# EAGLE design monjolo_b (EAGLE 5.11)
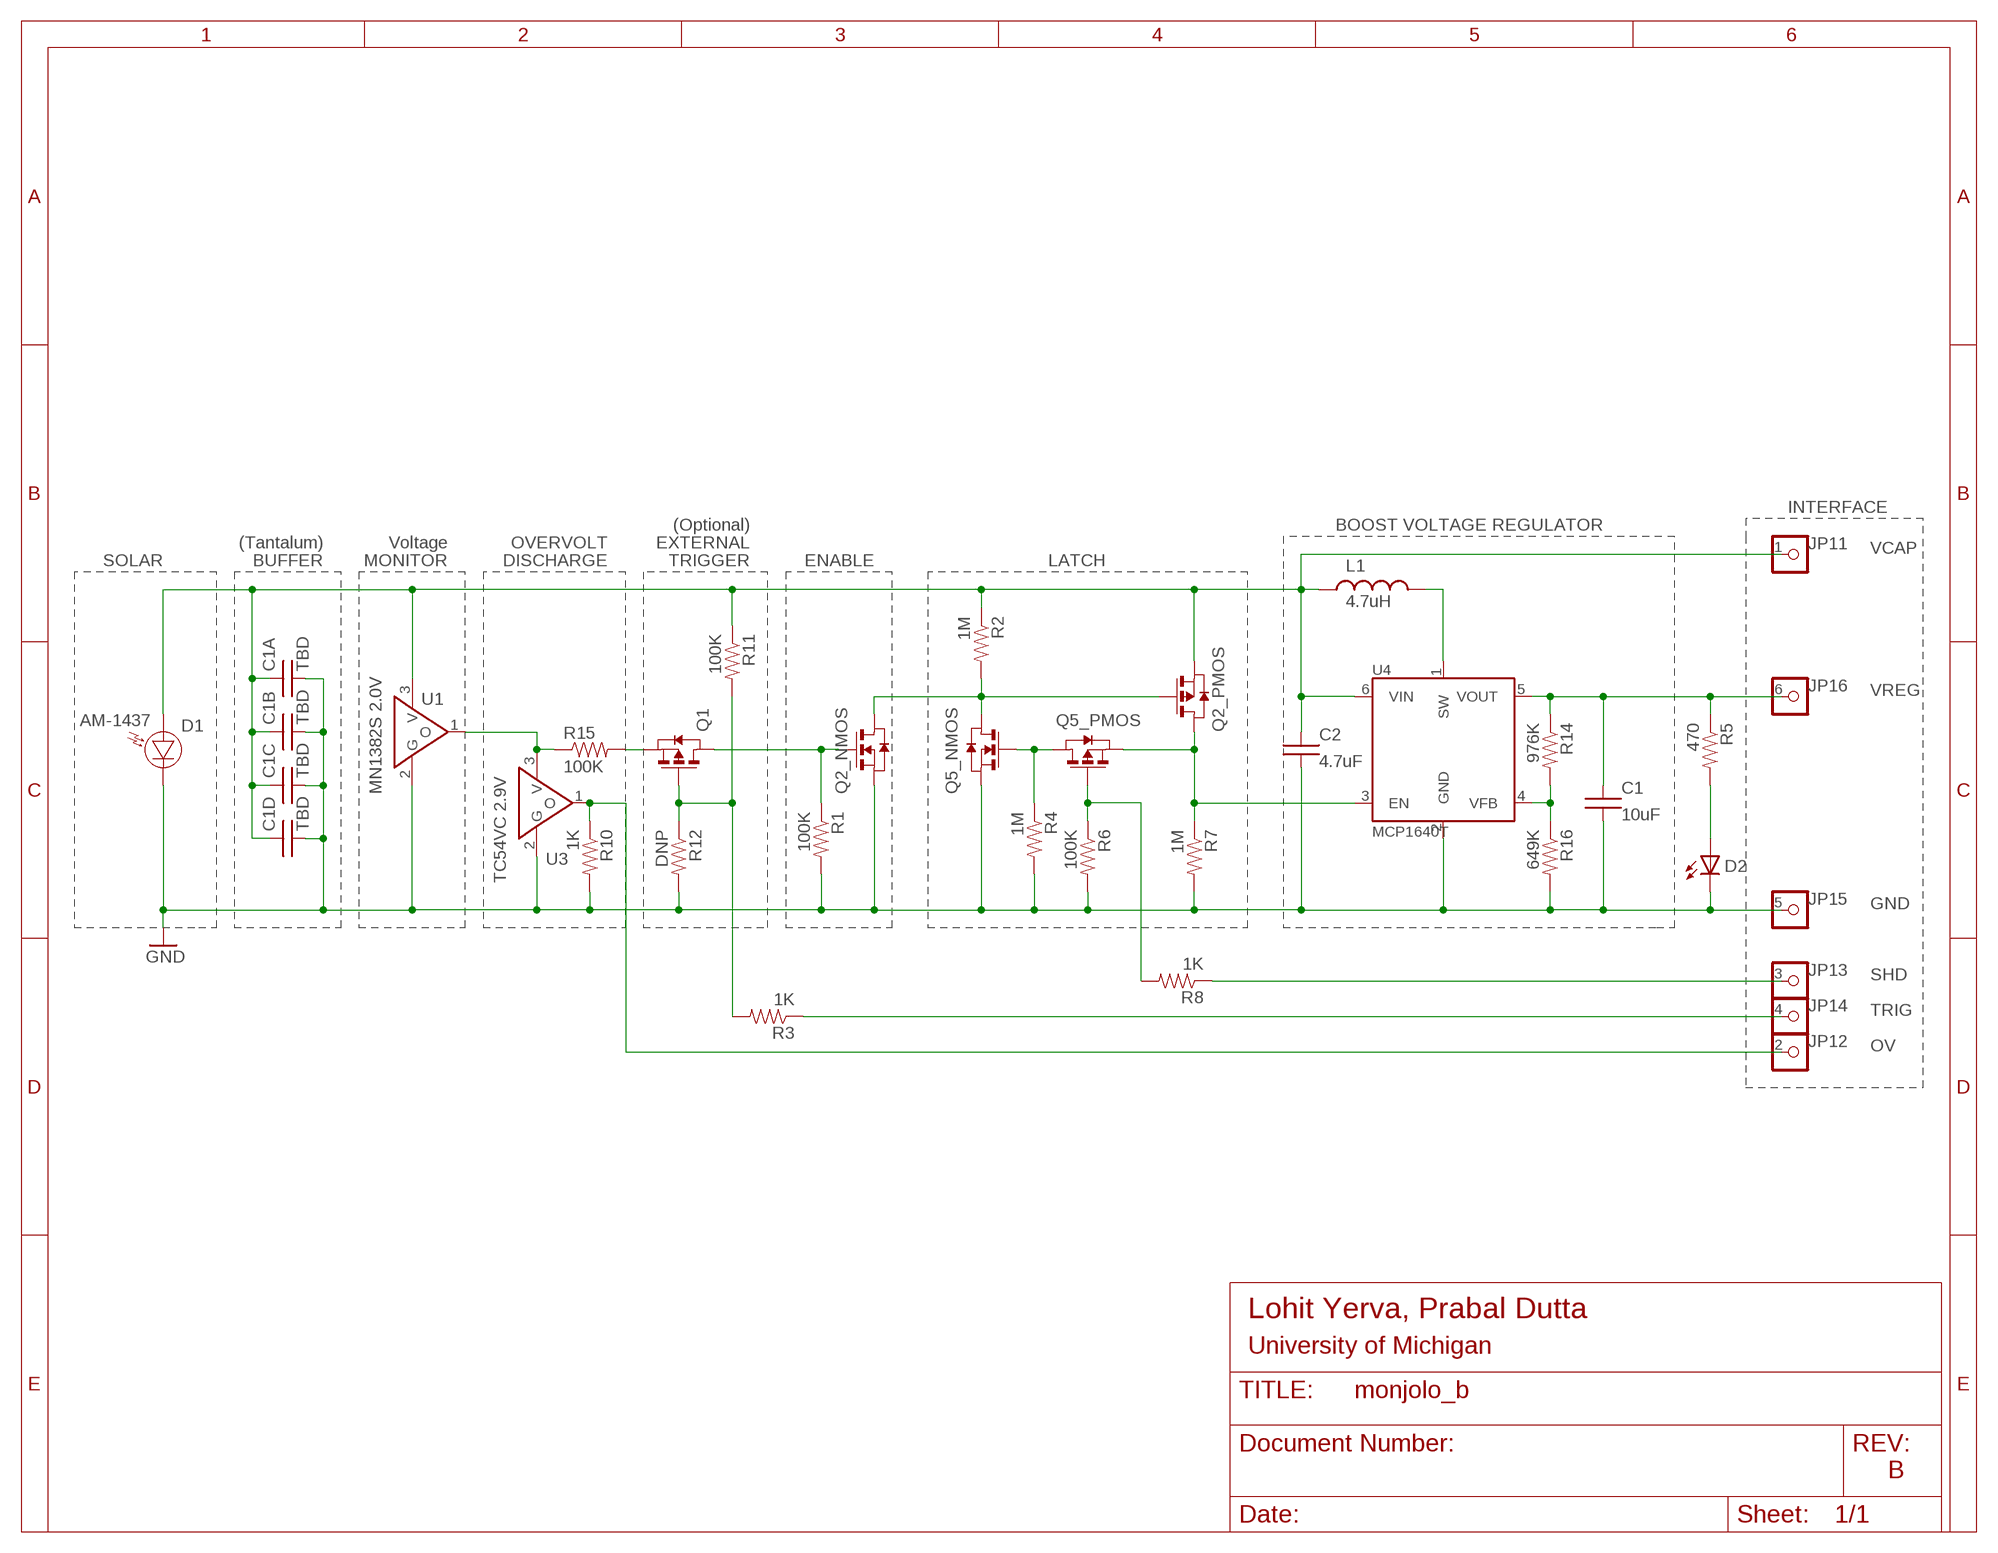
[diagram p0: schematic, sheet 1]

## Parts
C1  10uF  CAP  [R0603B]
C1A  TBD  C1206  [C1206]
C1B  TBD  C1206  [C1206]
C1C  TBD  C1206  [C1206]
C1D  TBD  C1206  [C1206]
C2  4.7uF  CAP  [R0603B]
D1  AM-1437  [AM-1437]
D2  LED0603  [LED-0603]
JP1  PINHD6  [HD6]
L1  4.7uH  L-US  [L2828]
Q1  PMOSSOT23  [SOT-23]
Q2  DUAL_MOSFET_NP  [TSOP-6]
Q5  DUAL_MOSFET_NP  [TSOP-6]
R1  100K  RESISTOR  [R0603B]
R2  1M  RESISTOR  [R0603B]
R3  1K  RESISTOR  [R0603B]
R4  1M  RESISTOR  [R0603B]
R5  470  RESISTOR  [R0603B]
R6  100K  RESISTOR  [R0603B]
R7  1M  RESISTOR  [R0603B]
R8  1K  RESISTOR  [R0603B]
R10  1K  RESISTOR  [R0603B]
R11  100K  RESISTOR  [R0603B]
R12  DNP  RESISTOR  [R0603B]
R14  976K  RESISTOR  [R0603B]
R15  100K  RESISTOR  [R0603B]
R16  649K  RESISTOR  [R0603B]
U1  MN1382S 2.0V  MN1382S  [MINI-3DC]
U3  TC54VC 2.9V  MN1382S  [MINI-3DC]
U4  MCP1640T  MCP1640  [SOT-23-6]

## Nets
GND: C1.2 C1A.2 C1B.2 C1C.2 C1D.2 C2.2 D1.-(C) D2.C JP1.5 Q2.5(_NMOS:S) Q5.5(_NMOS:S) R1.2 R4.2 R6.2 R7.2 R10.2 R12.2 R16.2 U1.2(G) U3.2(G) U4.2(GND)
N$1: R14.2 R16.1 U4.4(VFB)
N$2: Q1.2(S) R15.2
N$4: L1.2 U4.1(SW)
N$5: D2.A R5.2
N$6: Q5.1(_NMOS:G) Q5.4(_PMOS:D) R4.1
N$7: Q1.1(D) Q2.1(_NMOS:G) R1.1
N$8: JP1.3 R8.1
N$9: Q2.3(_PMOS:G) Q2.6(_NMOS:D) Q5.6(_NMOS:D) R2.2
N$12: Q5.3(_PMOS:G) R6.1 R8.2
N$13: JP1.2 R10.1 U3.1(O)
N$14: R15.1 U1.1(O) U3.3(V)
N$15: Q1.3(G) R3.2 R11.2 R12.1
N$16: JP1.4 R3.1
N$18: Q2.4(_PMOS:D) Q5.2(_PMOS:S) R7.1 U4.3(EN)
VCAP: C1A.1 C1B.1 C1C.1 C1D.1 C2.1 D1.+(A) JP1.1 L1.1 Q2.2(_PMOS:S) R2.1 R11.1 U1.3(V) U4.6(VIN)
VREG: C1.1 JP1.6 R5.1 R14.1 U4.5(VOUT)

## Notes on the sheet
- INTERFACE
- (Optional) | BOOST VOLTAGE REGULATOR
- (Tantalum) | Voltage | OVERVOLT | EXTERNAL
- SOLAR | BUFFER | MONITOR | DISCHARGE | TRIGGER | ENABLE | LATCH | VCAP
- VREG
- GND
- SHD
- TRIG
- OV
- Lohit Yerva, Prabal Dutta
- University of Michigan
- B

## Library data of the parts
C1 C2 = Gecko:CAP
C1A C1B C1C C1D = umich:C
D1 = umich:AM-1437
D2 = umich:LED: LEDs
JP1 = Gecko:PINHD6
L1 = Gecko:L-US
Q1 = berkeley-epic:PMOSSOT23: MOS FET
Q2 Q5 =  gecko_vreg_revC:DUAL_MOSFET_NP
R1-R8 R10-R12 R14-R16 = Gecko:RESISTOR
U1 U3 = umich:MN1382S
U4 = Gecko:MCP1640

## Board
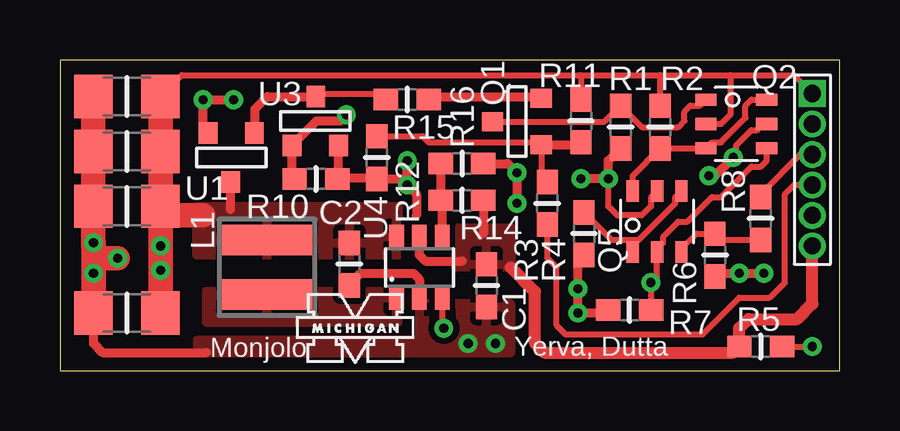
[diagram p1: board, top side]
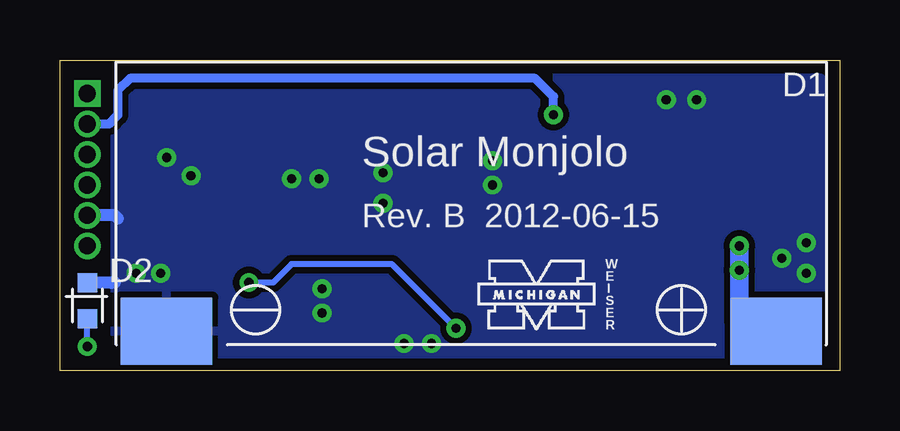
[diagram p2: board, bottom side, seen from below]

Size 32.51 x 12.95 mm. Coordinates in mm from the lower left corner, seen from the top.
Outline: 32.51,0 32.51,12.95 0,12.95 0,0 32.51,0
Copper layers (1*16): Top 0.0178mm / dielectric 1.4986mm / Bottom 0.0178mm
Design rules "SSC-EAGLE-2Lyr_v1.0.0.3 *": minimum track width 6mil, minimum drill 14mil, track to track 6mil, track to pad 6mil, pad to pad 6mil, via to via 6mil, smd to smd 6mil, copper to edge 20mil, drill to drill 16mil, minimum pad ring 8mil, minimum via ring 8mil, stop-mask expansion 3mil, vias tented up to drill 20mil, thermal gap 10mil

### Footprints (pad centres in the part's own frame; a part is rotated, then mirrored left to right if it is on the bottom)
R0603B = smd 1.016 x 0.889: 1 -0.889,0; 2 0.889,0
C1206 = smd 1.6 x 1.8: 1 -1.4,0; 2 1.4,0
AM-1437 = smd 3.81 x 2.794: + 12.7,-5.334; - -12.7,-5.334
LED-0603 = smd 0.8 x 0.8: A 0,-0.75; C 0,0.75
HD6 = drill 0.711 pad 1.016 square: 1 -2.54,0 | drill 0.711 pad 1.016 round: 2 -1.27,0; 3 0,0; 4 1.27,0; 5 2.54,0; 6 3.81,0
L2828 = smd 1.27 x 3.81: 1 -1.143,0; 2 1.143,0
SOT-23 = smd 0.787 x 0.889: 1 0.025,-1.016; 2 -0.94,1.016; 3 0.991,1.016
TSOP-6 = smd 0.508 x 0.889: 1 -1.016,-1.27; 2 0,-1.27; 3 1.016,-1.27; 4 1.016,1.27; 5 0,1.27; 6 -1.016,1.27
MINI-3DC = smd 0.787 x 0.889: 1 -0.991,-1.016; 2 0.94,-1.016; 3 0,1.016
SOT-23-6 = smd 0.61 x 1.016: 1 -0.953,-1.27; 2 0,-1.27; 3 0.953,-1.27; 4 0.953,1.27; 5 0,1.27; 6 -0.953,1.27

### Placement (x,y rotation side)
C1  17.78,3.56 270 top
C1A  2.79,11.43 180 top
C1B  2.79,9.14 180 top
C1C  2.79,6.86 180 top
C1D  2.79,2.41 180 top
C2  12.06,4.45 270 top
D1  15.37,6.99 0 bottom
D2  31.37,2.92 0 bottom
JP1  31.37,9.02 270 top
L1  8.64,4.32 270 top
Q1  19.05,10.41 270 top
Q2  28.19,10.29 270 top
Q5  24.89,6.22 0 top
R1  23.37,10.16 270 top
R2  25.02,10.16 270 top
R3  20.32,6.99 90 top
R4  21.84,5.71 270 top
R5  29.21,1.02 0 top
R6  27.3,4.83 270 top
R7  23.75,2.54 180 top
R8  29.21,6.35 270 top
R10  10.67,8 0 top
R11  21.72,10.41 270 top
R12  13.21,8.89 270 top
R14  16.76,7.11 180 top
R15  14.48,11.3 0 top
R16  16.76,8.64 0 top
U1  7.11,8.89 180 top
U3  10.67,10.41 0 top
U4  14.99,4.32 0 top
U$1  [UMICH]  15.18,1.52 0 bottom
U$2  [UMICH]  9.78,0.13 0 top

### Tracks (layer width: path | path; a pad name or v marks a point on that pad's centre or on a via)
GND  (via drill 0.38)
  Top 0.254: Q2.5 29.34,10.29 29.08,10.03 28.83,10.03 28.19,9.4 28.19,9.02 v28.07,8.89 | v22.86,8 22.86,6.86 23.24,6.48 24.26,6.48 24.64,6.86 24.64,7.24 Q5.5
  Top 0.381: C2.2 12.09,3.62 12.53,4.06 14.73,4.06 14.99,3.81 U4.2 | v14.48,7.75 14.86,7.37 14.86,6.48 | 1.4,2.29 1.4,1.14 1.78,0.76 6.1,0.76 | U1.2 5.97,10.11 v5.97,11.3 v7.24,11.3 | 11.61,8.05 U3.2 | R10.2 11.61,8.05 | 11.61,8.05 13.16,8.05 R12.2 14.48,8 v14.48,7.75 | v14.48,7.75 v14.48,8.76 | R16.2 18.67,8.64 v19.05,8.26 v19.05,6.99 | R1.2 22.86,8.76 v22.86,8 v21.72,8 | R4.2 21.59,4.57 v21.59,3.43 v21.59,2.41 23.11,2.41 R7.2 | R6.2 27.43,4.06 v28.32,4.06 v29.34,4.06 | v28.07,8.89 27.3,8.13 v27.05,8.13
  Top 0.508: v1.4,5.33 1.39,5.21
  Top 0.762: C1D.2
  Top 1.016: C1A.2 C1B.2 C1C.2 1.39,5.21 | 1.4,4.7 v1.4,5.33 | 1.4,4.7 v2.41,4.7 | C1D.2 v1.4,4.06 1.4,4.7
  Bottom 0.508: JP1.5 30.23,6.48 30.1,6.35 | D2.C 30.36,3.67 30.23,3.68
  other vias: 18.16,1.14 17.02,1.14
  pour Bottom (isolate 0.254): 0.76,0.64 0.76,12.19 30.23,12.19 30.23,0.64
  pour Top (isolate 0.254): 5.71,1.27 5.71,0.76 18.8,0.76 18.8,2.79 14.99,2.79 14.99,1.27
N$1
  Top 0.381: R16.1 R14.2 15.94,7.11 U4.4
N$2
  Top 0.381: Q1.2 19.99,11.43 15.49,11.43 R15.2
N$4
  pour Top (isolate 0.254): 14.1,3.3 6.1,3.3 6.1,2.03 14.1,2.03
N$5  (via drill 0.38)
  Top 0.254: R5.2 v31.37,1.02
  Bottom 0.254: v31.37,1.02 D2.A
N$6
  Top 0.254: Q5.4 25.65,7.24 25.65,6.99 24.13,5.46 23.88,5.46 | 23.88,5.46 Q5.1 | R4.1 22.99,5.46 23.88,5.46
N$7
  Top 0.254: R1.1 23.37,11.25 | Q1.1 22.71,10.39 R1.1 | R1.1 24.26,10.16 25.78,10.16 26.04,10.41 26.04,10.79 26.29,11.05 26.67,11.05 Q2.1
N$8
  Top 0.254: JP1.3 30.86,9.02 29.21,7.37 R8.1
N$9
  Top 0.254: Q2.6 28.83,11.3 28.57,11.05 28.57,10.54 27.56,9.53 27.18,9.53 Q2.3 R2.2 23.88,8.13 Q5.6
N$12
  Top 0.254: Q5.3 25.91,5.08 26.54,5.71 R6.1 27.56,5.46 R8.2
N$13  (via drill 0.38)
  Top 0.381: R10.1 9.68,8.1 U3.1 10.69,10.41 11.68,10.41 v11.94,10.67
  Bottom 0.381: v11.94,10.67 11.94,11.43 12.7,12.19 29.59,12.19 30.1,11.68 30.1,10.67 30.48,10.29 JP1.2
N$14
  Top 0.254: R15.1 13.34,11.56 10.79,11.56 U3.3
  Top 0.381: U3.3 8.64,11.43 8.13,10.92 8.13,9.93 U1.1
N$15
  Top 0.254: R12.1 15.11,9.78 15.37,9.53 19.96,9.53 Q1.3 20.07,8.13 R3.2
  Top 0.381: Q1.3 21.61,9.42 R11.2
N$16
  Top 0.254: JP1.4 30.61,7.75 30.23,7.37 30.23,3.68 29.59,3.05 28.32,3.05 26.8,1.52 21.08,1.52 20.7,1.91 20.7,4.32 20.32,4.7 R3.1
N$18  (via drill 0.38)
  Top 0.254: U4.3 15.94,1.84 v16,1.78 | v24.64,3.68 24.77,3.68 | v24.64,3.68 R7.1 | v24.64,3.68 24.89,3.94 Q5.2 24.89,5.08 25.15,5.33 25.15,5.59 25.78,6.22 26.16,6.22 27.18,7.24 27.56,7.24 28.83,8.51 29.21,8.51 29.46,8.76 Q2.4
  Bottom 0.254: v16,1.78 18.67,4.45 22.86,4.45 23.62,3.68 v24.64,3.68
VCAP  (via drill 0.38)
  Top 0.254: C1A.1 5.08,12.32 21.72,12.32 | 21.72,12.32 R11.1 | JP1.1 30.61,12.32 27.94,12.32 | 21.72,12.32 25.02,12.32 | 25.02,12.32 27.94,12.32 | 25.02,12.32 R2.1 | Q2.2 27.56,10.29 27.94,10.67 27.94,12.32
  Top 0.381: 7.11,6.73 U1.3
  Top 0.762: C1D.1 4.19,2.29 | C1C.1 4.19,6.48
  Top 1.016: C1A.1 C1B.1 C1C.1 | C1D.1 v4.19,4.19 v4.19,5.21 4.19,6.48 5.97,6.48
  Bottom 0.762: v4.19,5.21 v4.19,4.19 4.19,2.08 D1.+
  pour Top (isolate 0.254): 5.71,6.86 14.1,6.86 14.1,4.83 5.71,4.83
VREG
  Top 0.381: U4.5 14.99,4.83 15.24,4.57 16.76,4.57 | R14.1 17.65,5.71
  Top 0.508: 18.8,4.32 19.81,3.3 19.81,1.14 20.19,0.76 28.07,0.76 R5.1 28.32,1.78 28.7,2.16 30.73,2.16 31.37,2.79 JP1.6
  pour Top (isolate 0.254): 16.51,5.97 18.8,5.97 18.8,4.32 16.51,4.32

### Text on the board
tPlace: Monjolo | Yerva, Dutta
bPlace: Solar Monjolo | Rev. B 2012-06-15 | E | W | I | S | E | R
tValues: VCAP | N_P_MOS | OV | PMOS | SHD | TRIG | N_P_MOS | GND | VREG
